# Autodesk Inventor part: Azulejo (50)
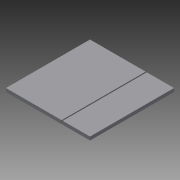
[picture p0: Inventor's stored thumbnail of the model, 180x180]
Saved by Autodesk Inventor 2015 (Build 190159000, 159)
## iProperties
Created: 2015-04
Part Number: Azulejo (50)
Material: Genérico
Document SubType Name: Modeling
Designer: Felipe
Density: 1 g/cm^3
Appearance: Padrão
Author: Felipe
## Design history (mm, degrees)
sketch "Sketch1"
  geometry: L1 (-5999.978, 1162.687)-(-5915.126, 1162.687); L2 (6980.022, 1162.687)-(6895.169, 1162.687); L3 (-1034.12, -6357.313)-(-1063.775, -6417.313); L4 (-5519.978, 1582.687)-(-6306.841, 1582.687); L5 (5000.022, -4857.313)-(6000.022, -4857.313); L6 (6000.022, -4857.313)-(6000.022, -6277.313); L7 (6000.022, -4837.313)-(5000.022, -4837.313); L8 (5000.022, -4837.313)-(5000.022, -3357.313); L9 (5000.022, -3357.313)-(6000.022, -3357.313); L10 (6000.022, -3357.313)-(6000.022, -4837.313); L11 (6000.022, -3337.313)-(5000.022, -3337.313); L12 (5000.022, -3337.313)-(5000.022, -1857.313); L13 (5000.022, -1857.313)-(6000.022, -1857.313); L14 (6000.022, -1857.313)-(6000.022, -3337.313); L15 (6000.022, -1837.313)-(5000.022, -1837.313); L16 (5000.022, -1837.313)-(5000.022, -357.313); L17 (5000.022, -357.313)-(6000.022, -357.313); L18 (6000.022, -357.313)-(6000.022, -1837.313); L19 (4000.022, -4837.313)-(3500.022, -4837.313); L20 (3500.022, -4837.313)-(3500.022, -3357.313); L21 (3500.022, -3357.313)-(4000.022, -3357.313); L22 (4000.022, -3357.313)-(4000.022, -4837.313); L23 (4000.022, -3337.313)-(3500.022, -3337.313); L24 (3500.022, -3337.313)-(3500.022, -1857.313); L25 (2000.022, 2662.687)-(2480.022, 2662.687); L26 (500.022, 2662.687)-(1980.022, 2662.687); L27 (-999.978, 2662.687)-(480.022, 2662.687); L28 (3500.022, -1857.313)-(4000.022, -1857.313); L29 (4000.022, -1857.313)-(4000.022, -3337.313); L30 (4000.022, -1837.313)-(3500.022, -1837.313); L31 (3500.022, -1837.313)-(3500.022, -357.313); L32 (3500.022, -357.313)-(4000.022, -357.313); L33 (4000.022, -357.313)-(4000.022, -1837.313); L34 (-5519.978, 1142.687)-(-5519.978, -337.313); L35 (6500.022, -337.313)-(6500.022, 1142.687); L36 (6480.022, 2662.687)-(5000.022, 2662.687); L37 (5000.022, 2642.687)-(6480.022, 2642.687); L38 (6480.022, 1142.687)-(6480.022, -337.313); L39 (6480.022, -337.313)-(5000.022, -337.313); L40 (5000.022, -337.313)-(5000.022, 1142.687); L41 (7965.922, 2662.687)-(6500.022, 2662.687); L42 (6500.022, 2642.687)-(7965.922, 2642.687); L43 (4980.022, 2662.687)-(3500.022, 2662.687); L44 (3500.022, 2642.687)-(4980.022, 2642.687); L45 (4980.022, 1142.687)-(4980.022, -337.313); L46 (4980.022, -337.313)-(3500.022, -337.313); L47 (3500.022, -337.313)-(3500.022, 1142.687); L48 (3500.022, -1837.313)-(3500.022, -357.313); L49 (3500.022, -3337.313)-(3500.022, -1857.313); L50 (3500.022, -4837.313)-(3500.022, -3357.313); L51 (3500.022, -6257.313)-(3500.022, -4857.313); L52 (4000.022, -6277.313)-(3500.022, -6277.313); L53 (3500.022, -6277.313)-(3500.022, -4857.313); L54 (3480.022, 1162.687)-(2000.022, 1162.687); L55 (2000.022, 1142.687)-(3480.022, 1142.687); L56 (3480.022, 1142.687)-(3480.022, -337.313); L57 (3480.022, -337.313)-(2000.022, -337.313); L58 (2000.022, -337.313)-(2000.022, 1142.687); L59 (3480.022, -357.313)-(3480.022, -1837.313); L60 (3480.022, -1857.313)-(3480.022, -3337.313); L61 (3480.022, -3357.313)-(3480.022, -4837.313); L62 (3480.022, -4857.313)-(3480.022, -6277.313); L63 (3500.022, -4857.313)-(4000.022, -4857.313); L64 (1980.022, 1162.687)-(500.022, 1162.687)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; 4 further points
  constraints: 1802 end point, 96 point on line, 2 other
extrude "Extrusion1" new body sketch "Sketch1" distance "d0" = 60; taper "d1" = 0 deg
extrude "Extrusion2" new body sketch "Sketch1" distance "d2" = 60; taper "d3" = 0 deg
body "Solid1"
body "Solid2"
